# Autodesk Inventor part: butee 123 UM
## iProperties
Shininess: 88.0
Angle Display Precision: 2
Document Length Units: 11269
Document Angle Units: 11279
Document Time Units: 11290
Document Mass Units: 11283
Document Length Units Precision: 3
Document Angle Units Precision: 2
Created: 2002-02
Part Number: butee 123 UM
Material: Par défaut
Document SubType Name: Modélisation
Designer: Administrateur
Density: 0.0
Volumn: 0.0
Area: 0.0
PropertySet Name: Model Information
Control State: 0
Master: False
Checked Out: False
Author: Administrateur
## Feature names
1. Extrusion1
2. Perçage1 [Hole]
3. Perçage2 [Hole]
